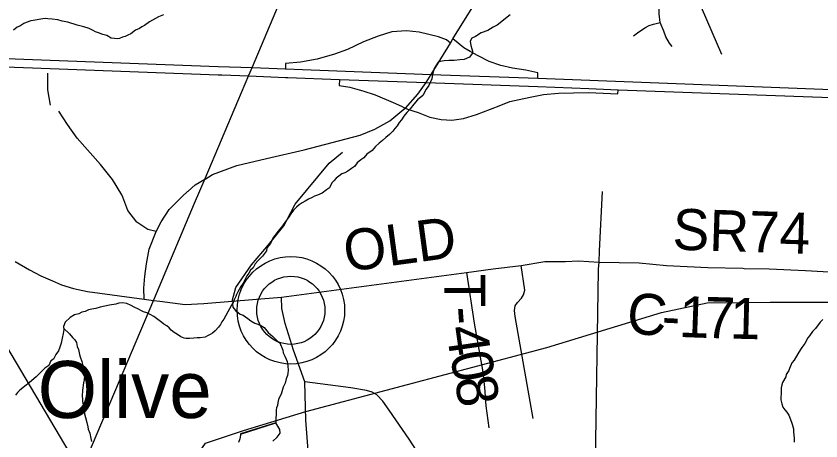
# Model space of a CAD drawing. Extents: x 0 to 34, y 0 to 22.
# Drawn here: x 7.873 to 8.429, y 16.017 to 16.311 of the extents above; entities that cross this region are included whole.
import ezdxf

# ---------------------------------------------------------------- set-up
doc = ezdxf.new("R2010")
doc.units = 0
for name, color, linetype in [('GM_X_Corporation', 7, 'Continuous'), ('GM_X_County_Road', 7, 'Continuous'), ('GM_X_County_Road_Text', 7, 'Continuous'), ('GM_X_Interchange_Ramps', 7, 'Continuous'), ('GM_X_Minor_Lake', 7, 'Continuous'), ('GM_X_Minor_River', 7, 'Continuous'), ('GM_X_Rail_Line', 7, 'Continuous'), ('GM_X_State_Route', 7, 'Continuous'), ('GM_X_Township', 7, 'Continuous'), ('GM_X_Township_Road', 7, 'Continuous'), ('GM_X_Township_Road_Text', 7, 'Continuous'), ('GM_X_Unincorporated', 7, 'Continuous'), ('GM_X_Unincorporated_Location', 7, 'Continuous'), ('GM_X_Unincorporated_Text', 7, 'Continuous')]:
    doc.layers.add(name, color=color, linetype=linetype)

msp = doc.modelspace()

# ---------------------------------------------------------------- linework, layer by layer
at = {"layer": 'GM_X_Corporation'}
msp.add_lwpolyline([(8.07623, 16.37167), (8.03576, 16.27564), (8.03331, 16.26987), (8.02574, 16.25202), (8.00303, 16.19841), (7.99579, 16.18133), (7.96749, 16.11454), (7.70278, 15.48987), (7.56193, 15.15588), (7.53361, 15.08872), (7.48819, 14.98101), (7.48543, 14.97447), (7.44826, 14.88634)], dxfattribs=at)
at = {"layer": 'GM_X_County_Road'}
for points in [[(8.15853, 16.26881), (8.1597, 16.27071), (8.17295, 16.29239), (8.17469, 16.29529), (8.19034, 16.32044)], [(7.99152, 16.18996), (7.9964, 16.1943), (8.00314, 16.19815), (8.00342, 16.19831), (8.00843, 16.20148), (8.02513, 16.20766), (8.04584, 16.2125), (8.07189, 16.21851), (8.11056, 16.2286), (8.12075, 16.23281), (8.13094, 16.23865), (8.14072, 16.24653), (8.14175, 16.24736), (8.1503, 16.25691), (8.1562, 16.26499), (8.15853, 16.26881)], [(7.96105, 16.11509), (7.961, 16.12282), (7.9615, 16.13117), (7.96284, 16.13969), (7.96467, 16.14971), (7.96948, 16.16201), (7.97286, 16.16875), (7.97853, 16.17726), (7.98739, 16.18628), (7.99114, 16.18962), (7.99152, 16.18996)], [(8.37604, 16.13649), (8.39345, 16.13612), (8.41858, 16.13493), (8.4635, 16.13236), (8.48012, 16.13117), (8.49378, 16.13128), (8.50649, 16.13211), (8.5082, 16.13257), (8.50972, 16.1329), (8.51108, 16.13341), (8.51252, 16.13397), (8.51395, 16.13458), (8.51537, 16.13521), (8.51677, 16.13589), (8.51866, 16.13687), (8.54545, 16.14996), (8.56853, 16.16121), (8.58578, 16.1694), (8.58994, 16.17137), (8.5972, 16.17482)], [(7.87193, 16.14127), (7.88179, 16.13557), (7.88964, 16.13129), (7.89772, 16.12773), (7.9039, 16.12499), (7.91233, 16.12262), (7.92196, 16.12036), (7.96105, 16.11509), (7.9676, 16.11428), (7.972, 16.11374)], [(7.972, 16.11374), (7.98956, 16.11157), (8.00241, 16.11213), (8.0221, 16.11388), (8.036, 16.11496), (8.056, 16.11649), (8.18411, 16.13365), (8.20241, 16.13606), (8.22186, 16.13848), (8.23832, 16.14124), (8.25259, 16.14124), (8.26157, 16.1417), (8.27572, 16.14086), (8.30347, 16.14032), (8.32234, 16.13848), (8.3509, 16.13711), (8.37504, 16.13651), (8.37604, 16.13649)], [(8.07489, 16.00736), (8.07299, 16.03138), (8.07222, 16.05798), (8.06444, 16.07981), (8.05875, 16.09824), (8.05636, 16.10871), (8.056, 16.11649)], [(8.23535, 15.89172), (8.19739, 15.94067), (8.18557, 15.9569), (8.1796, 15.96526), (8.16754, 15.98293), (8.16002, 15.99409), (8.14432, 16.01838), (8.13064, 16.03838), (8.12624, 16.04462), (8.12206, 16.04902), (8.11883, 16.05086), (8.11486, 16.05189), (8.10407, 16.05372), (8.07222, 16.05798)]]:
    msp.add_lwpolyline(points, dxfattribs=at)
at = {"layer": 'GM_X_Interchange_Ramps'}
for points in [[(8.17295, 16.29239), (8.17012, 16.29472), (8.16459, 16.29669), (8.15134, 16.29986), (8.14263, 16.30085), (8.13235, 16.30011), (8.12306, 16.29709), (8.11277, 16.29314), (8.1017, 16.28799), (8.0928, 16.28463), (8.08074, 16.28127), (8.06927, 16.27909), (8.05879, 16.2783), (8.05883, 16.27452)], [(8.18663, 16.28663), (8.18216, 16.28912), (8.17818, 16.29221), (8.17469, 16.29529)], [(8.23338, 16.26805), (8.23342, 16.27189), (8.22502, 16.27365), (8.21596, 16.27498), (8.20779, 16.27697), (8.19961, 16.27962), (8.1921, 16.2836), (8.18663, 16.28663)], [(8.09614, 16.26713), (8.09596, 16.26302), (8.10326, 16.26183), (8.10975, 16.26)], [(8.10975, 16.26), (8.11224, 16.25929), (8.12086, 16.25646), (8.13341, 16.25117), (8.13907, 16.24871), (8.14071, 16.24785), (8.14175, 16.24736)], [(8.14175, 16.24736), (8.1433, 16.2467), (8.15056, 16.24428), (8.15872, 16.24115), (8.16656, 16.23947), (8.17381, 16.23896), (8.1819, 16.24014), (8.19092, 16.24292), (8.20053, 16.24672), (8.20769, 16.2495), (8.21393, 16.25186), (8.22057, 16.25328), (8.22807, 16.25497), (8.23727, 16.25678), (8.24775, 16.25781), (8.26834, 16.25808), (8.2888, 16.2573), (8.28897, 16.26004)]]:
    msp.add_lwpolyline(points, dxfattribs=at)
at = {"layer": 'GM_X_Minor_Lake'}
for points in [[(8.02783, 16.02173), (8.05207, 16.02966)], [(8.05207, 16.02966), (8.02786, 16.02188)], [(8.05022, 16.01699), (8.0531, 16.01961), (8.05523, 16.02242), (8.05489, 16.0249), (8.05359, 16.02738), (8.05207, 16.02966)], [(8.02786, 16.02188), (8.02766, 16.02093), (8.02724, 16.01847), (8.02645, 16.01601)]]:
    msp.add_lwpolyline(points, dxfattribs=at)
at = {"layer": 'GM_X_Minor_River'}
for points in [[(7.97446, 16.31195), (7.97101, 16.31049), (7.96487, 16.30717), (7.96141, 16.30457), (7.95949, 16.30366), (7.95795, 16.30254), (7.95508, 16.30126), (7.952, 16.29884), (7.94989, 16.29793), (7.94797, 16.29682), (7.94625, 16.29647), (7.94415, 16.29556), (7.94244, 16.2954), (7.94054, 16.29543), (7.93826, 16.29585), (7.93525, 16.29761), (7.9326, 16.29823), (7.92958, 16.29942), (7.9275, 16.30022), (7.9258, 16.30101), (7.92316, 16.30239), (7.91938, 16.3036), (7.91484, 16.30482), (7.90841, 16.30683), (7.90443, 16.30747), (7.90141, 16.30848), (7.89761, 16.30892), (7.89457, 16.30917), (7.89306, 16.30938), (7.89115, 16.30923), (7.88448, 16.30801), (7.88276, 16.30766), (7.87951, 16.30658), (7.87798, 16.30584), (7.8751, 16.30418), (7.87338, 16.30345), (7.87068, 16.30122)], [(8.21416, 16.31194), (8.21108, 16.30934), (8.20857, 16.30729), (8.2053, 16.30468), (8.20243, 16.3034), (8.19878, 16.30118), (8.19419, 16.29955), (8.19015, 16.29696), (8.18766, 16.29586), (8.18668, 16.29379), (8.187, 16.29074), (8.18773, 16.28844), (8.18808, 16.28673), (8.18805, 16.28521), (8.18611, 16.28258), (8.18247, 16.28112), (8.17942, 16.28079), (8.17561, 16.28029), (8.17181, 16.28036), (8.16857, 16.28003), (8.16591, 16.2797), (8.16438, 16.27915), (8.16164, 16.27483), (8.16043, 16.27066), (8.16, 16.26763), (8.15802, 16.2631), (8.15608, 16.26047), (8.15373, 16.25614), (8.15025, 16.25316), (8.14754, 16.25016), (8.14502, 16.24697), (8.14269, 16.24435), (8.14075, 16.24172), (8.13899, 16.23928), (8.13744, 16.23741), (8.13607, 16.23515), (8.13452, 16.23327), (8.13316, 16.2314), (8.13084, 16.22915), (8.12814, 16.22692), (8.12602, 16.22506), (8.1237, 16.223), (8.12119, 16.22077), (8.11886, 16.21795), (8.11521, 16.21555), (8.11308, 16.21292), (8.11096, 16.21163), (8.10846, 16.20939), (8.1067, 16.20695), (8.10459, 16.20565), (8.1019, 16.2038), (8.09998, 16.20269), (8.09787, 16.20178), (8.09576, 16.20029), (8.09383, 16.19881), (8.09228, 16.19712), (8.09093, 16.19562), (8.08935, 16.19223), (8.08723, 16.19093), (8.08434, 16.18851), (8.08109, 16.18724), (8.07898, 16.18632), (8.07726, 16.1854), (8.07477, 16.1843), (8.07246, 16.18301), (8.07035, 16.18191), (8.06843, 16.18042), (8.0665, 16.17874), (8.06437, 16.17669), (8.06262, 16.17425), (8.06087, 16.17162), (8.05892, 16.1688), (8.05678, 16.16598), (8.05483, 16.16336), (8.05289, 16.16111), (8.05153, 16.15923), (8.05037, 16.15773), (8.04859, 16.15358), (8.04606, 16.15058), (8.04565, 16.14868), (8.04293, 16.14493), (8.04138, 16.14324), (8.03983, 16.14175), (8.03789, 16.1395), (8.03652, 16.13686), (8.03478, 16.13518), (8.0336, 16.13311), (8.03224, 16.13123), (8.03106, 16.12897), (8.0295, 16.12634), (8.02794, 16.12389), (8.02676, 16.12182), (8.02597, 16.12012), (8.02499, 16.11843), (8.02459, 16.11691), (8.02341, 16.11465), (8.02222, 16.11163), (8.02237, 16.10954), (8.02424, 16.10741)], [(8.02294, 16.11347), (8.01615, 16.10128), (8.01479, 16.0994), (8.01381, 16.09752), (8.01245, 16.09583), (8.01012, 16.09321), (8.00838, 16.09172), (8.00666, 16.0908), (8.00493, 16.08969), (8.0034, 16.08895), (7.99997, 16.08844), (7.99787, 16.08829), (7.9954, 16.08814), (7.99254, 16.088), (7.99026, 16.08785), (7.98874, 16.08807), (7.98648, 16.08906), (7.98422, 16.09062), (7.98178, 16.09218), (7.9799, 16.09374), (7.97841, 16.09528), (7.97672, 16.09664), (7.97484, 16.09782), (7.97334, 16.09898), (7.97146, 16.10035), (7.96977, 16.10171), (7.96771, 16.10308), (7.96526, 16.10445), (7.963, 16.10563), (7.96073, 16.10643), (7.95884, 16.10741), (7.95715, 16.1082), (7.95432, 16.10959), (7.95206, 16.11077), (7.94904, 16.11215), (7.9462, 16.11258), (7.94372, 16.11243), (7.94162, 16.11171), (7.93705, 16.11103), (7.93075, 16.10962), (7.92769, 16.10872), (7.92502, 16.1082), (7.92273, 16.10786), (7.92024, 16.10657), (7.91796, 16.10623), (7.91604, 16.10512), (7.91298, 16.10422), (7.90991, 16.10257), (7.90643, 16.0992), (7.90524, 16.09618), (7.90559, 16.09427), (7.90516, 16.09143), (7.90435, 16.08821), (7.90371, 16.08461), (7.90272, 16.08196), (7.90191, 16.07932), (7.89997, 16.07688), (7.8984, 16.07367), (7.89648, 16.07238), (7.89509, 16.06936), (7.8924, 16.0675), (7.88969, 16.0647), (7.88641, 16.06152), (7.88178, 16.05742), (7.87946, 16.05556), (7.87522, 16.05221), (7.87348, 16.05053), (7.87213, 16.04884)], [(8.02424, 16.10741), (8.02611, 16.10586), (8.02762, 16.10488), (8.0295, 16.10409), (8.03289, 16.10175), (8.03495, 16.10019), (8.03777, 16.09862), (8.03966, 16.09783), (8.0423, 16.09664), (8.04418, 16.09546), (8.04679, 16.09219), (8.04848, 16.09064), (8.05016, 16.08927), (8.05334, 16.08618), (8.05484, 16.08501), (8.05704, 16.07984), (8.0572, 16.07812), (8.05849, 16.07563), (8.05941, 16.07371), (8.05995, 16.07199), (8.06047, 16.06913), (8.06079, 16.06589), (8.06057, 16.06399), (8.06016, 16.06229), (8.05936, 16.06002), (8.05855, 16.05699), (8.05737, 16.05435), (8.05576, 16.04944), (8.05498, 16.04774), (8.05399, 16.04566), (8.05357, 16.04358), (8.05335, 16.04168), (8.05275, 16.03998), (8.05235, 16.03847), (8.05207, 16.02966)], [(8.43036, 16.10108), (8.42861, 16.09921), (8.42531, 16.0949), (8.42337, 16.09284), (8.42123, 16.08983), (8.42007, 16.08833), (8.4181, 16.08456), (8.41596, 16.08175), (8.41499, 16.08024), (8.41323, 16.07723), (8.41068, 16.0729), (8.40913, 16.07103), (8.40735, 16.06726), (8.40695, 16.06574), (8.40519, 16.06311), (8.40497, 16.0614), (8.40263, 16.05745), (8.40203, 16.05594), (8.40162, 16.05386), (8.40158, 16.05157), (8.40147, 16.04549), (8.402, 16.04263), (8.40291, 16.04052), (8.40421, 16.0386), (8.40551, 16.03706), (8.407, 16.03494), (8.40882, 16.03015), (8.40936, 16.02862), (8.41007, 16.02538), (8.41023, 16.02347), (8.41072, 16.01871), (8.41068, 16.01624)], [(7.90544, 16.09506), (7.90953, 16.09116), (7.91158, 16.08865), (7.91326, 16.08691), (7.91437, 16.08518), (7.91489, 16.08251), (7.91562, 16.08022), (7.91632, 16.07678), (7.91686, 16.07525), (7.91814, 16.072), (7.91849, 16.07028), (7.91938, 16.06646), (7.91972, 16.06436), (7.91988, 16.06265), (7.91963, 16.05923), (7.91922, 16.05734), (7.91857, 16.05221), (7.91831, 16.04803), (7.91846, 16.04594), (7.91843, 16.04442), (7.91913, 16.04079), (7.91981, 16.03584), (7.92053, 16.03335), (7.92142, 16.02992), (7.92213, 16.02686), (7.92248, 16.02514), (7.92358, 16.02246), (7.92427, 16.01865), (7.92481, 16.01674)]]:
    msp.add_lwpolyline(points, dxfattribs=at)
at = {"layer": 'GM_X_Rail_Line'}
for points in [[(7.98969, 15.86454), (7.97792, 15.89676), (7.9471, 15.94564), (7.90633, 16.01458), (7.86621, 16.08248), (7.84214, 16.11721), (7.82041, 16.14516), (7.79233, 16.17448), (7.74628, 16.21987), (7.7111, 16.24634), (7.67665, 16.2653), (7.63308, 16.28236), (7.40377, 16.36953)], [(7.98969, 15.86454), (7.98939, 15.937), (7.99075, 15.98395), (7.99292, 16.00032), (8.00357, 16.01545), (8.02974, 16.02429), (8.07295, 16.03744), (8.23965, 16.08179), (8.31899, 16.106), (8.35056, 16.11271), (8.39414, 16.11308), (8.44742, 16.1131)]]:
    msp.add_lwpolyline(points, dxfattribs=at)
at = {"layer": 'GM_X_State_Route'}
msp.add_line((8.06043, 16.26859), (8.09614, 16.26713), dxfattribs=at)
for points in [[(7.18919, 16.44995), (7.32593, 16.39984), (7.40223, 16.37174), (7.45175, 16.3538), (7.52297, 16.32765), (7.59326, 16.30177), (7.60884, 16.2964), (7.6232, 16.29201), (7.63527, 16.28894), (7.64744, 16.28664), (7.66126, 16.28444), (7.67376, 16.28335), (7.68637, 16.28269), (7.74997, 16.28045), (7.82817, 16.27721), (7.89614, 16.27468), (8.0124, 16.27041), (8.0149, 16.27031)], [(7.40618, 16.37651), (7.4557, 16.35857), (7.52339, 16.33344), (7.59369, 16.30756), (7.60926, 16.30218), (7.62362, 16.2978), (7.63569, 16.29473), (7.64786, 16.29242), (7.66168, 16.29023), (7.67418, 16.28913), (7.68547, 16.28854), (7.74888, 16.28602), (7.82927, 16.28303), (7.89607, 16.28055), (8.01233, 16.27627), (8.03587, 16.27538), (8.05883, 16.27452)], [(8.05883, 16.27452), (8.1597, 16.27071), (8.23338, 16.26805), (8.45435, 16.25949), (8.4754, 16.25906), (8.49492, 16.25796), (8.51214, 16.25664), (8.52684, 16.25412), (8.54022, 16.25149), (8.5559, 16.24754), (8.5673, 16.24392), (8.57801, 16.2398), (8.5915, 16.23453), (8.60795, 16.22773), (8.63623, 16.2159)], [(8.0149, 16.27031), (8.03343, 16.26961), (8.0589, 16.26865), (8.06043, 16.26859)], [(8.09614, 16.26713), (8.1562, 16.26499), (8.23338, 16.26229), (8.26869, 16.26087), (8.28897, 16.26004), (8.44898, 16.25418), (8.4765, 16.25308), (8.4958, 16.25231), (8.50929, 16.25143), (8.52508, 16.24935), (8.53715, 16.24727), (8.5525, 16.24354), (8.55297, 16.24341)]]:
    msp.add_lwpolyline(points, dxfattribs=at)
at = {"layer": 'GM_X_Township'}
msp.add_lwpolyline([(8.07623, 16.37167), (8.03576, 16.27564), (8.03331, 16.26987), (8.02574, 16.25202), (8.00303, 16.19841), (7.99579, 16.18133), (7.96749, 16.11454), (7.70278, 15.48987), (7.56193, 15.15588), (7.53361, 15.08872), (7.48819, 14.98101), (7.48543, 14.97447), (7.44826, 14.88634)], dxfattribs=at)
at = {"layer": 'GM_X_Township_Road'}
for p, q in [((8.36068, 16.28436), (8.34057, 16.33069)), ((8.32634, 16.29005), (8.32538, 16.29119))]:
    msp.add_line(p, q, dxfattribs=at)
for points in [[(8.32538, 16.29119), (8.32442, 16.29232), (8.3219, 16.29681), (8.32042, 16.30056), (8.31805, 16.30672), (8.31726, 16.31254), (8.31724, 16.31867), (8.31655, 16.32352)], [(8.29946, 16.2975), (8.30237, 16.29952), (8.3073, 16.30292), (8.31036, 16.3045), (8.31327, 16.30554), (8.31805, 16.30672)], [(7.89626, 16.24952), (7.89457, 16.25996), (7.89445, 16.27165)], [(7.94643, 16.18565), (7.9458, 16.18729), (7.93922, 16.19797), (7.93101, 16.20824), (7.91478, 16.22652), (7.908, 16.23597), (7.90222, 16.24523)], [(8.0626, 16.17519), (8.06556, 16.18086), (8.08902, 16.20933), (8.09824, 16.21681)], [(7.96948, 16.16201), (7.96366, 16.16347), (7.95606, 16.1684), (7.9499, 16.17661), (7.94643, 16.18565)], [(8.27536, 16.13602), (8.27572, 16.14086), (8.27596, 16.14853), (8.27809, 16.18964)], [(8.0221, 16.11388), (8.02449, 16.12328), (8.03535, 16.13892), (8.04708, 16.15283), (8.05773, 16.16587), (8.0626, 16.17519)], [(8.23013, 16.03251), (8.21779, 16.10318), (8.21726, 16.10729), (8.21771, 16.11063), (8.21923, 16.11285), (8.22199, 16.11578), (8.22356, 16.11808), (8.22434, 16.12129), (8.22186, 16.13848)], [(8.23535, 15.89172), (8.24303, 15.89701), (8.25128, 15.90301), (8.25766, 15.9092), (8.26207, 15.91408), (8.26554, 15.91943), (8.26864, 15.92496), (8.27276, 15.93481), (8.27314, 15.95207), (8.2733, 16.00266), (8.27528, 16.13506), (8.27536, 16.13602)], [(8.18411, 16.13365), (8.1894, 16.09854), (8.19527, 16.06458), (8.19655, 16.05396), (8.1973, 16.04132), (8.19949, 16.02619)]]:
    msp.add_lwpolyline(points, dxfattribs=at)
at = {"layer": 'GM_X_Unincorporated'}
for radius in [0.0372, 0.02358]:
    msp.add_circle((8.06258, 16.10747), radius, dxfattribs=at)
at = {"layer": 'GM_X_Unincorporated_Location'}
msp.add_line((8.06258, 16.10747), (8.06258, 16.10747), dxfattribs=at)

# ---------------------------------------------------------------- texts
at = {"layer": 'GM_X_County_Road_Text'}
for s, height, rotation, p in [('SR74', 0.028409, 358.1805, (8.32626, 16.14951)), ('OLD', 0.028409, 7.7497, (8.10103, 16.134)), ('C', 0.02841, 354.9353, (8.29408, 16.09174)), ('1', 0.02841, 357.8945, (8.33057, 16.08904)), ('7', 0.02841, 358.4194, (8.34835, 16.08839)), ('1', 0.02841, 358.5754, (8.36592, 16.08791)), ('-', 0.02841, 357.331, (8.31861, 16.0896))]:
    msp.add_text(s, height=height, rotation=rotation, dxfattribs=at).set_placement(p)
at = {"layer": 'GM_X_Township_Road_Text'}
for s, rotation, p in [('T', 270.0387, (8.16868, 16.13269)), ('-', 274.1332, (8.16878, 16.10923)), ('4', 278.2277, (8.16986, 16.09539)), ('0', 280.2749, (8.17254, 16.07698)), ('8', 280.2749, (8.17566, 16.05976))]:
    msp.add_text(s, height=0.02841, rotation=rotation, dxfattribs=at).set_placement(p)
at = {"layer": 'GM_X_Unincorporated_Text'}
msp.add_text('Olive', height=0.039489, rotation=0, dxfattribs=at).set_placement((7.88753, 16.0329))

doc.saveas('drawing.dxf')
